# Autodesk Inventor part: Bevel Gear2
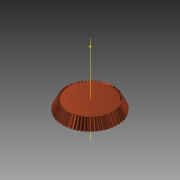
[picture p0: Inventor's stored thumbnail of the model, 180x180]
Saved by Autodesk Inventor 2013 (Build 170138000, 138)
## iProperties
Created: 2008-07
Part Number: Bevel Gear2
Material: Steel, Mild
Document SubType Name: Modeling
Designer: tangg
Categories: <?xml version="1.0" encoding="UTF-16"?> <MemberInstance><Categories><FamilyTemplate><FamilyTemplateParameter ValueType="xs:double" Id="1" ObjectReferenceKey="da
Mass: 60.9118 g
Surface Area: 34.3074 cm^2
Volume: 7.7496 cm^3
Density: 7.86 g/cm^3
CustomPartVersion: 1
Author: tangg
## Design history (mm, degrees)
node "Top Point"
node "Mesh Plane2"
sketch "Teeth Body Sketch"
  geometry: L1 (0, 0)-(19.196, -41.108); L2 (19.196, -41.108)-(20.579, -40.431); L3 (20.579, -40.431)-(0, 0); L4 (19.95, -40.739)-(0, 0); L5 (15.81, -33.858)-(16.949, -33.301); L6 (19.196, -41.108)-(15.81, -33.858); L7 (20.579, -40.431)-(16.949, -33.301); L8 (0, -49.33)-(0, 8.222) reference; L9 (0, -40.739)-(20.579, -40.739)
  constraints: 16 end point, 4 point on line, 3 perpendicular, 2 collinear, 1 horizontal alignment, 1 vertical alignment
  dimensions: "d0" = 39.9 diameter of L4.start L8 (= da_de); "d1" = 38.3912 diameter of L1.end L8 (= da_dfe); "d2" = 41.15733 diameter of L2.end L8 (= da_dae); "d3" = 8 distance between parallel lines of L2 L5 (= da_b); "d4" = 40.43108 vertical distance of L2.end L1.start (= da_ve)
revolve "Teeth Body" sketch "Teeth Body Sketch" stored, may be unused: angle "d5" = 90 deg
node "Start Point"
node "Tooth Plane"
sketch "Start Sketch"
  geometry: L1 (0, -48.837)-(0, 14.035) reference; L2 (-0.213, -0.185)-(0.213, -0.185); A1 r 8.268 centre (-8.214, -2.267) between (-0.213, -0.185) and (-1.118, 1.975); A2 r 8.268 centre (8.214, -2.267) between (1.118, 1.975) and (0.213, -0.185); A3 r 23.376 centre (0, -21.374) between (1.118, 1.975) and (-1.118, 1.975); 1 further point
  constraints: 6 point on circle, 3 centre point, 3 symmetric about line, 2 end point, 1 coincident, 1 perpendicular, 1 other
  dimensions: "d7" = 8.26757 radius of A1 (= fd_rr); "d8" = 8.21392 horizontal distance of point (0, -21.374) A1.centre (= fd_x); "d9" = 19.10643 vertical distance of point (0, -21.374) A1.centre (= fd_y); "d57" = 23.37567 radius of A3 (= 0.5 x fd_dva + 0.3 x da_he); "d58" = 21.18887 distance from line of A3.centre L2 (= 0.5 x fd_dva - 1.12 x da_he)
node "End Point"
  node "End Plane"
sketch "3D Sketch Right"
  node "Helical Curve Right" dims "d65" = 1118.46783 (computed from da_dm, da_delta, da_beta), "d66" = 31.5, "d67" = 39.9 (= da_de), "d68" = -4.55377 (= -da_delta), "d69" = 7.25392 (computed from fd_loft, da_delta)
node "End Plane Right"
sketch "End Sketch Right"
  geometry: L1 (0, -22.799)-(0, 5.523) reference; L2 (-0.175, -0.821)-(0.175, -0.821); A1 r 6.804 centre (-6.76, -2.535) between (-0.175, -0.821) and (-0.92, 0.956); A2 r 6.804 centre (6.76, -2.535) between (0.92, 0.956) and (0.175, -0.821); A3 r 19.237 centre (0, -18.258) between (0.92, 0.956) and (-0.92, 0.956); 1 further point
  constraints: 6 point on circle, 3 centre point, 3 symmetric about line, 2 end point, 1 coincident, 1 perpendicular, 1 other
  dimensions: "d70" = 6.75958 horizontal distance of A3.centre A1.centre (computed from fd_x, fd_ratio); "d71" = 15.72347 vertical distance of point (0, -18.258) A1.centre (computed from fd_y, fd_ratio); "d72" = 6.80373 radius of A1 (computed from fd_rr, fd_ratio); "d73" = 17.4372 distance from line of point (0, -18.258) L2 (computed from d58, fd_ratio); "d74" = 19.23681 radius of A3 (computed from d57, fd_ratio)
feature "Loft Right" sketch "End Sketch Right" dims "d75" = 0, "d76" = 90 deg, "d77" = 0, "d78" = 90 deg, "d79" = 0, "d80" = 90 deg, "d85" = 20, "da_teethtype" = 0 [user parameter]
sketch "3D Sketch Left"
  node "Helical Curve Left" dims "d26" = 1118.46783 (computed from da_dm, da_delta, da_beta), "d27" = 7.25392 (computed from fd_loft, da_delta), "d28" = 39.9 (= da_de), "d29" = -4.55377 (= -da_delta)
node "End Plane Left"
sketch "End Sketch Left" dims "d56" = 15.22216 (derived)
  geometry: L1 (0, -37.75)-(0, 8.865) reference; L2 (-0.175, -0.821)-(0.175, -0.821); A1 r 6.804 centre (-6.76, -2.535) between (-0.175, -0.821) and (-0.92, 0.956); A2 r 6.804 centre (6.76, -2.535) between (0.92, 0.956) and (0.175, -0.821); A3 r 19.237 centre (0, -18.258) between (0.92, 0.956) and (-0.92, 0.956); 2 further points; 1 other entity
  constraints: 6 point on circle, 3 centre point, 3 symmetric about line, 2 end point, 1 coincident, 2 other
  dimensions: "d30" = 6.80373 radius of A1 (computed from fd_rr, fd_ratio); "d31" = 6.75958 horizontal distance of point (0, -18.258) A1.centre (computed from fd_x, fd_ratio); "d32" = 15.72347 vertical distance of A1.centre point (0, -18.258) (computed from fd_y, fd_ratio); "d61" = 19.23681 radius of A3 (computed from d57, fd_ratio); "d62" = 17.4372 distance from line of point (0, -18.258) L2 (computed from d58, fd_ratio)
feature "Loft Left" sketch "End Sketch Left" dims "d35" = 0, "d37" = 0, "d39" = 0, "d40" = 90 deg, "d63" = 90 deg, "d64" = 90 deg, "d84" = 10, "da_teethtype" = 0 [user parameter]
sketch "Body Sketch"
  geometry: L1 (0, -42.558)-(0, -32.408) reference; L2 (19.196, -41.108)-(15.81, -33.858) reference; L3 (15.81, -33.858)-(0, -33.858); L4 (19.196, -41.108)-(0, -41.108)
  constraints: 4 end point, 2 perpendicular, 2 point on line
revolve "Fix Body" sketch "Body Sketch" stored, may be unused: angle "d46" = 90 deg
sketch "Sketch6"
  geometry: L1 (19.95, -40.739)-(0, 0) reference; L2 (0, -48.887)-(0, 8.148) reference
feature "Pitch Diameter" sketch "Sketch6" dims angle "d47" = 90 deg
body "Solid1"
feature "Loft" dims "d17" = 0, "d18" = 90 deg, "d19" = 0, "d20" = 90 deg, "d89" = 0, "da_teethtype" = 0 [user parameter]
pattern_circular "Circular Pattern" dims angle "d22" = 360 deg, "d88" = 0, "da_teethtype" = 0 [user parameter]
pattern_circular "Circular Pattern Right" dims angle "d82" = 360 deg, "da_teethtype" = 0 [user parameter]
pattern_circular "Circular Pattern Left" dims angle "d42" = 360 deg, "da_teethtype" = 0 [user parameter]
sketch "End Sketch"
  geometry: L1 (0, -44.037)-(0, 12.922) reference; L2 (-0.175, 0.019)-(0.175, 0.019); A1 r 6.804 centre (-6.76, -1.695) between (-0.175, 0.019) and (-0.92, 1.796); A2 r 6.804 centre (6.76, -1.695) between (0.92, 1.796) and (0.175, 0.019); A3 r 19.237 centre (0, -17.418) between (0.92, 1.796) and (-0.92, 1.796); 1 further point
  constraints: 6 point on circle, 3 centre point, 3 symmetric about line, 2 end point, 1 coincident, 1 other
  dimensions: "d12" = 6.80373 radius of A1 (computed from fd_rr, fd_ratio); "d15" = 6.75958 horizontal distance of A1.centre point (0, -17.418) (computed from fd_x, fd_ratio); "d16" = 15.72347 vertical distance of A1.centre point (0, -17.418) (computed from fd_y, fd_ratio); "d59" = 19.23681 radius of A3 (computed from d57, fd_ratio); "d60" = 17.4372 distance from line of A3.centre L2 (computed from d58, fd_ratio)
body "Srf1"
other parameters: "da_b" = 8 [user parameter; used in 2 equation terms], "da_de" = 39.9 [user parameter; used in 4 equation terms], "da_dae" = 41.15733 [user parameter; used in 2 equation terms], "da_dfe" = 38.3912 [user parameter; used in 1 equation term], "da_le" = 45.36148 [user parameter; used in 1 equation term], "da_omega" = 45 deg [user parameter], "da_beta" = 0 [user parameter; used in 2 equation terms], "da_delta" = 4.55377 [user parameter; used in 8 equation terms], "da_alpha" = 20 deg [user parameter; used in 1 equation term], "da_he" = 1.54 [user parameter; used in 4 equation terms], "da_ve" = 40.43108 [user parameter; used in 1 equation term], "fd_dv" = 44.42735 (computed from da_de, da_delta) [user parameter; used in 1 equation term], "fd_dva" = 45.82735 (computed from da_dae, da_delta) [user parameter; used in 3 equation terms], "fd_dvb" = 41.74805 (computed from fd_dv, da_alpha) [user parameter; used in 2 equation terms], "da_zv" = 634.67638 [user parameter; used in 1 equation term], "fd_loft" = 8.077 (= da_b + 0.05 x da_he) [user parameter; used in 4 equation terms], "fd_ratio" = 8.22941 (computed from da_le, fd_loft) [user parameter; used in 15 equation terms], "fd_rr" = 8.26757 (computed from fd_dd, fd_dvb) [user parameter; used in 6 equation terms], "fd_angle" = 0.2475 (computed from da_zv) [user parameter; used in 4 equation terms], "fd_x1" = 0.54972 (computed from da_dvw, fd_angle) [user parameter; used in 1 equation term], "fd_y1" = 22.20687 (computed from da_dvw, fd_angle) [user parameter; used in 1 equation term], "fd_x2" = 7.6642 (computed from fd_rr, fd_angle2, fd_angle) [user parameter; used in 1 equation term], "fd_y2" = 3.10044 (computed from fd_rr, fd_angle2, fd_angle) [user parameter; used in 1 equation term], "fd_x" = 8.21392 (= fd_x1 + fd_x2) [user parameter; used in 4 equation terms], "fd_y" = 19.10643 (= fd_y1 - fd_y2) [user parameter; used in 4 equation terms], "fd_angle2" = 3.5966 (computed from fd_dvb, fd_dd) [user parameter; used in 2 equation terms], "fd_dd" = 44.90335 (= fd_dva - 0.6 x da_he) [user parameter; used in 2 equation terms], "da_dvw" = 44.42735 [user parameter; used in 2 equation terms], "d11" = -8.077 (= -fd_loft), "da_dm" = 36.3816 [user parameter; used in 2 equation terms], "da_x" = 0 [user parameter], "da_m" = 0.7 [user parameter], "d51" = 0.55116 (computed from da_z)
